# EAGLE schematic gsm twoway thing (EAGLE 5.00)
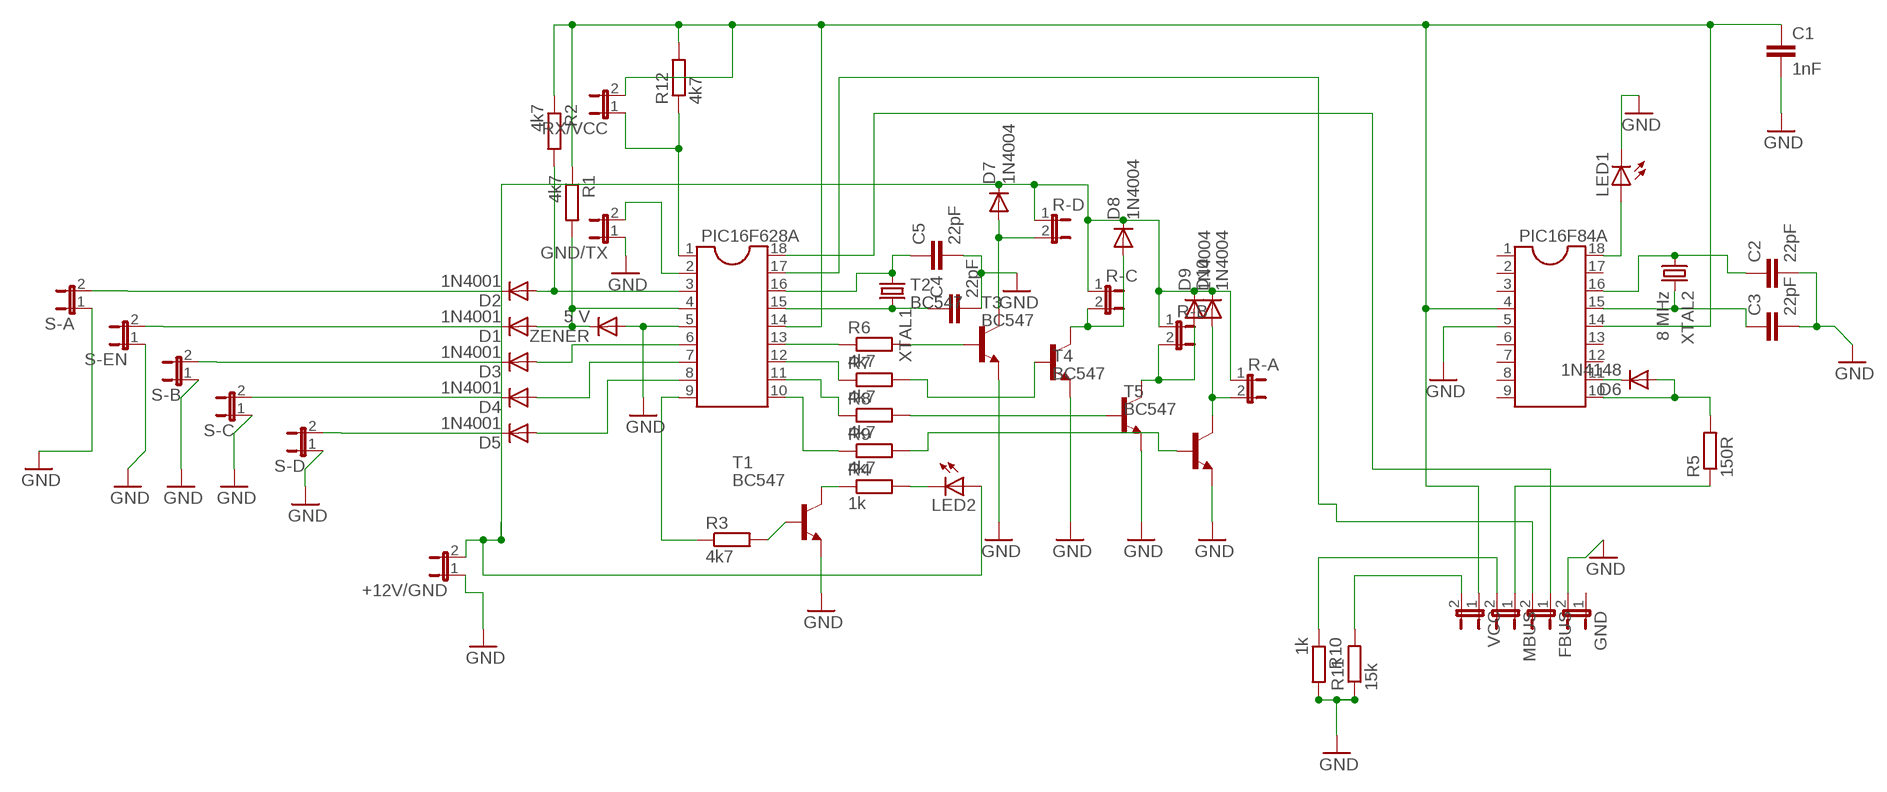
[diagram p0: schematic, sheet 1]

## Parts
+12V/GND  JP1E  [JP1]
C1  1nF  C2,5-3  [C2.5-3]
C2  22pF  C2,5-3  [C2.5-3]
C3  22pF  C2,5-3  [C2.5-3]
C4  22pF  C2,5-3  [C2.5-3]
C5  22pF  C2,5-3  [C2.5-3]
D1  1N4001  1N4004  [DO41-10]
D2  1N4001  1N4004  [DO41-10]
D3  1N4001  1N4004  [DO41-10]
D4  1N4001  1N4004  [DO41-10]
D5  1N4001  1N4004  [DO41-10]
D6  1N4148  [DO35-10]
D7  1N4004  [DO41-10]
D8  1N4004  [DO41-10]
D9  1N4004  [DO41-10]
D10  1N4004  [DO41-10]
FBUS  JP1E  [JP1]
GND  JP1E  [JP1]
GND/TX  JP1E  [JP1]
LED1  LED5MM  [LED5MM]
LED2  LED5MM  [LED5MM]
MBUS  JP1E  [JP1]
PIC16F84A  DIL18  [DIL18]
PIC16F628A  DIL18  [DIL18]
R1  4k7  R-EU_0207/10  [0207/10]
R2  4k7  R-EU_0207/10  [0207/10]
R3  4k7  R-EU_0207/10  [0207/10]
R4  1k  R-EU_0207/10  [0207/10]
R5  150R  R-EU_0207/10  [0207/10]
R6  4k7  R-EU_0207/10  [0207/10]
R7  4k7  R-EU_0207/10  [0207/10]
R8  4k7  R-EU_0207/10  [0207/10]
R9  4k7  R-EU_0207/10  [0207/10]
R10  1k  R-EU_0207/10  [0207/10]
R11  15k  R-EU_0207/10  [0207/10]
R12  4k7  R-EU_0207/10  [0207/10]
R-A  JP1E  [JP1]
R-B  JP1E  [JP1]
R-C  JP1E  [JP1]
R-D  JP1E  [JP1]
RX/VCC  JP1E  [JP1]
S-A  JP1E  [JP1]
S-B  JP1E  [JP1]
S-C  JP1E  [JP1]
S-D  JP1E  [JP1]
S-EN  JP1E  [JP1]
T1  BC547  [TO92]
T2  BC547  [TO92]
T3  BC547  [TO92]
T4  BC547  [TO92]
T5  BC547  [TO92]
VCC  JP1E  [JP1]
XTAL1  CRYSTALHC49S  [HC49/S]
XTAL2  8 MHz  CRYSTALHC49S  [HC49/S]
ZENER  5 V  1N4004  [DO41-10]

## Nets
GND: +12V/GND.1 C1.2 C2.2 C3.2 C4.2 C5.2 GND.2 GND/TX.1 LED1.K(C) PIC16F84A.5 PIC16F628A.5 R10.2 R11.1 S-A.1 S-B.1 S-C.1 S-D.1 S-EN.1 T1.1(E) T2.1(E) T3.1(E) T4.1(E) T5.1(E) ZENER.A
N$1: C4.1 PIC16F628A.15 XTAL1.2
N$2: C5.1 PIC16F628A.16 XTAL1.1
N$3: PIC16F628A.13 R6.1
N$4: PIC16F628A.12 R7.1
N$5: PIC16F628A.11 R8.1
N$6: PIC16F628A.10 R9.1
N$7: R6.2 T2.2(B)
N$8: R9.2 T5.2(B)
N$9: R8.2 T4.2(B)
N$10: R7.2 T3.2(B)
N$11: D5.A PIC16F628A.8
N$12: D4.A PIC16F628A.7
N$13: D3.A PIC16F628A.6
N$14: D1.A PIC16F628A.4 R1.2 ZENER.C
N$15: D2.A PIC16F628A.3 R2.2
N$16: R4.1 T1.3(C)
N$17: GND/TX.2 PIC16F628A.2
N$18: PIC16F628A.1 R12.1 RX/VCC.1
N$19: D5.C S-D.2
N$20: C1.1 PIC16F84A.4 PIC16F84A.14 PIC16F628A.14 R1.1 R2.1 R12.2 RX/VCC.2 VCC.1
N$21: PIC16F628A.9 R3.1
N$22: R3.2 T1.2(B)
N$23: LED2.K(C) R4.2
N$24: R11.2 VCC.2
N$25: MBUS.2 R10.1
N$26: D10.A R-A.2 T5.3(C)
N$27: D9.A R-B.2 T4.3(C)
N$28: D8.A R-C.2 T3.3(C)
N$29: D7.A R-D.2 T2.3(C)
N$30: C3.1 PIC16F84A.15 XTAL2.2
N$31: C2.1 PIC16F84A.16 XTAL2.1
N$32: MBUS.1 R5.1
N$33: D4.C S-C.2
N$34: D6.A PIC16F84A.10 R5.2
N$35: D6.C PIC16F84A.11
N$36: FBUS.2 PIC16F628A.17
N$37: FBUS.1 PIC16F628A.18
N$38: D3.C S-B.2
N$39: D1.C S-EN.2
N$40: D2.C S-A.2
N$41: LED1.A PIC16F84A.18
N$42: +12V/GND.2 D7.C D8.C D9.C D10.C LED2.A R-A.1 R-B.1 R-C.1 R-D.1
Unconnected: GND.1 PIC16F84A.1 PIC16F84A.2 PIC16F84A.3 PIC16F84A.6 PIC16F84A.7 PIC16F84A.8 PIC16F84A.9 PIC16F84A.12 PIC16F84A.13 PIC16F84A.17

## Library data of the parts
+12V/GND FBUS GND GND/TX MBUS R-A R-B R-C R-D RX/VCC S-A S-B S-C S-D S-EN VCC = jumper:JP1E: JUMPER
C1-C5 = capacitor-wima:C: CAPACITOR
D1-D5 D7-D10 ZENER = diode:1N4004: DIODE
D6 = diode:1N4148: DIODE
LED1 LED2 = led:LED: LED
PIC16F84A PIC16F628A = ic-package:DIL18: Dual In Line / Socket
R1-R12 = resistor:R-EU_: RESISTOR, European symbol
T1-T5 = transistor-npn:BC547*: NPN Transistor
XTAL1 XTAL2 = crystal:CRYSTAL: CRYSTAL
